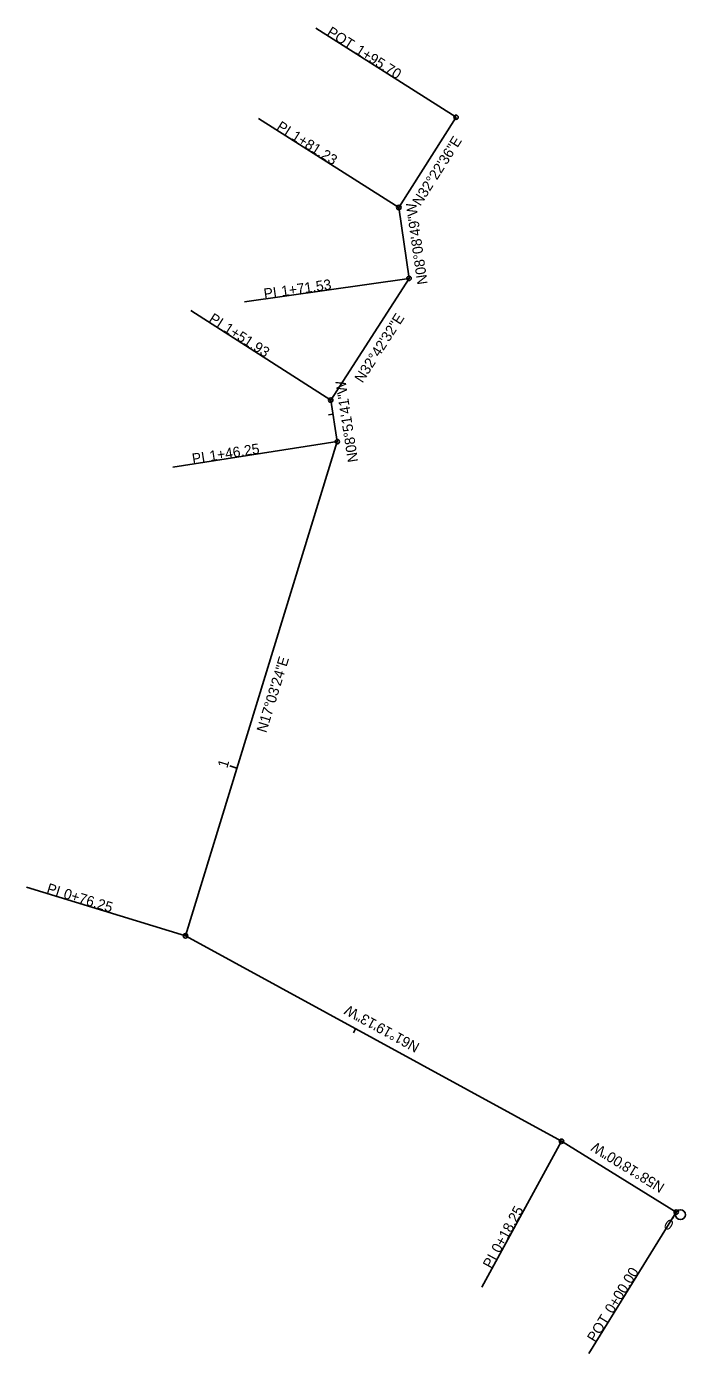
# Model space of a CAD drawing. Extents: x 2352406 to 2352495, y 726592 to 726772.
import ezdxf

# ---------------------------------------------------------------- set-up
doc = ezdxf.new("R2010")
doc.units = 0
for name, color, linetype in [('GE_P_Alignment', 7, 'Continuous'), ('GE_P_Driveway_CL', 7, 'Continuous'), ('SC_Scratch10', 7, 'Continuous'), ('SC_Scratch2', 7, 'Continuous'), ('SC_Scratch3', 7, 'Continuous'), ('SC_Scratch5', 7, 'Continuous'), ('VG_P_Cells', 7, 'Continuous')]:
    doc.layers.add(name, color=color, linetype=linetype)

msp = doc.modelspace()

# ---------------------------------------------------------------- linework, layer by layer
at = {"layer": 'GE_P_Alignment'}
for p, q in [((2352456.22, 726747.62), (2352463.97, 726759.83)), ((2352457.6, 726738.01), (2352456.22, 726747.62)), ((2352447.01, 726721.52), (2352457.6, 726738.01)), ((2352447.89, 726715.9), (2352447.01, 726721.52)), ((2352427.35, 726648.98), (2352447.89, 726715.9)), ((2352478.24, 726621.15), (2352427.35, 726648.98)), ((2352493.76, 726611.56), (2352478.24, 726621.15))]:
    msp.add_line(p, q, dxfattribs=at)
msp.add_circle((2352494.33, 726611.21), 0.672, dxfattribs=at)
at = {"layer": 'SC_Scratch2'}
for p, q in [((2352463.97, 726759.83), (2352444.97, 726771.88)), ((2352456.22, 726747.62), (2352437.22, 726759.67)), ((2352457.6, 726738.01), (2352435.33, 726734.82)), ((2352447.01, 726721.52), (2352428.08, 726733.68)), ((2352447.31, 726719.61), (2352446.71, 726719.52)), ((2352447.89, 726715.9), (2352425.65, 726712.44)), ((2352434.32, 726671.69), (2352433.36, 726671.98)), ((2352427.35, 726648.98), (2352405.84, 726655.58)), ((2352450.38, 726636.39), (2352450.09, 726635.86)), ((2352478.24, 726621.15), (2352467.44, 726601.41)), ((2352493.76, 726611.56), (2352481.94, 726592.42)), ((2352493.76, 726611.56), (2352493.24, 726610.71))]:
    msp.add_line(p, q, dxfattribs=at)
for centre in [(2352463.97, 726759.83), (2352456.22, 726747.62), (2352457.6, 726738.01), (2352447.01, 726721.52), (2352447.89, 726715.9), (2352427.35, 726648.98), (2352478.24, 726621.15), (2352493.76, 726611.56)]:
    msp.add_circle(centre, 0.3, dxfattribs=at)
at = {"layer": 'SC_Scratch5'}
for p, q in [((2352463.97, 726759.83), (2352444.97, 726771.88)), ((2352456.22, 726747.62), (2352437.22, 726759.67)), ((2352457.6, 726738.01), (2352435.33, 726734.82)), ((2352447.01, 726721.52), (2352428.08, 726733.68)), ((2352447.89, 726715.9), (2352425.65, 726712.44)), ((2352427.35, 726648.98), (2352405.84, 726655.58)), ((2352478.24, 726621.15), (2352467.44, 726601.41)), ((2352493.76, 726611.56), (2352481.94, 726592.42)), ((2352493.76, 726611.56), (2352493.24, 726610.71))]:
    msp.add_line(p, q, dxfattribs=at)
for centre in [(2352463.97, 726759.83), (2352456.22, 726747.62), (2352457.6, 726738.01), (2352447.01, 726721.52), (2352447.89, 726715.9), (2352427.35, 726648.98), (2352478.24, 726621.15), (2352493.76, 726611.56)]:
    msp.add_circle(centre, 0.3, dxfattribs=at)
at = {"layer": 'VG_P_Cells'}
for p, q in [((2352463.97, 726759.83), (2352444.97, 726771.88)), ((2352456.22, 726747.62), (2352437.22, 726759.67)), ((2352457.6, 726738.01), (2352435.33, 726734.82)), ((2352447.01, 726721.52), (2352428.08, 726733.68)), ((2352447.89, 726715.9), (2352425.65, 726712.44)), ((2352434.32, 726671.69), (2352433.75, 726671.87)), ((2352427.35, 726648.98), (2352405.84, 726655.58)), ((2352478.24, 726621.15), (2352467.44, 726601.41)), ((2352493.76, 726611.56), (2352481.94, 726592.42)), ((2352493.76, 726611.56), (2352493.24, 726610.71))]:
    msp.add_line(p, q, dxfattribs=at)
for centre in [(2352463.97, 726759.83), (2352456.22, 726747.62), (2352457.6, 726738.01), (2352447.01, 726721.52), (2352447.89, 726715.9), (2352427.35, 726648.98), (2352478.24, 726621.15), (2352493.76, 726611.56)]:
    msp.add_circle(centre, 0.3, dxfattribs=at)

# ---------------------------------------------------------------- texts
at = {"layer": 'GE_P_Driveway_CL'}
for s, rotation, p in [('N32°22\'36"E', 57.6234, (2352459.13, 726747.72)), ('N08°08\'49"W', 98.147, (2352460.13, 726737.28)), ('N32°42\'32"E', 57.2911, (2352451.3, 726723.76)), ('N08°51\'41"W', 98.8613, (2352450.73, 726713.22)), ('N17°03\'24"E', 72.9432, (2352438.27, 726676.39)), ('N61°19\'13"W', 151.3204, (2352459.15, 726634.32)), ('N58°18\'00"W', 148.2999, (2352492.31, 726615.28))]:
    msp.add_text(s, height=1.4, rotation=rotation, dxfattribs=at).set_placement(p)
at = {"layer": 'SC_Scratch10'}
for s, rotation, p in [('N32°22\'36"E', 57.6234, (2352459.13, 726747.72)), ('N08°08\'49"W', 98.147, (2352460.13, 726737.28)), ('N32°42\'32"E', 57.2911, (2352451.3, 726723.76)), ('N08°51\'41"W', 98.8613, (2352450.73, 726713.22)), ('N17°03\'24"E', 72.9432, (2352438.27, 726676.39)), ('N61°19\'13"W', 151.3204, (2352459.15, 726634.32)), ('N58°18\'00"W', 148.2999, (2352492.31, 726615.28))]:
    msp.add_text(s, height=1.4, rotation=rotation, dxfattribs=at).set_placement(p)
at = {"layer": 'SC_Scratch2'}
for s, rotation, p in [('POT', 327.6234, (2352446.37, 726771.02)), ('1+95.70', 327.6234, (2352450.23, 726768.57)), ('PI', 327.6234, (2352439.55, 726758.22)), ('1+81.23', 327.6234, (2352441.57, 726756.94)), ('1+71.53', 8.147, (2352440.41, 726735.57)), ('PI', 8.147, (2352438.04, 726735.23)), ('PI', 327.2911, (2352430.4, 726732.22)), ('1+51.93', 327.2911, (2352432.41, 726730.92)), ('1+46.25', 8.8613, (2352430.71, 726713.25)), ('PI', 8.8613, (2352428.35, 726712.88)), ('1', 72.9432, (2352432.99, 726671.61)), ('PI', 342.9432, (2352408.46, 726654.8)), ('0+76.25', 342.9432, (2352410.74, 726654.1)), ('0+18.25', 61.3204, (2352469.88, 726605.91)), ('0', 148.2999, (2352493.56, 726610.18)), ('PI', 61.3204, (2352468.73, 726603.81)), ('0+00.00', 58.2999, (2352485.18, 726597.71)), ('POT', 58.2999, (2352482.79, 726593.83))]:
    msp.add_text(s, height=1.4, rotation=rotation, dxfattribs=at).set_placement(p)
at = {"layer": 'SC_Scratch3'}
for s, rotation, p in [('N32°22\'36"E', 57.6234, (2352459.13, 726747.72)), ('N08°08\'49"W', 98.147, (2352460.13, 726737.28)), ('N32°42\'32"E', 57.2911, (2352451.3, 726723.76)), ('N08°51\'41"W', 98.8613, (2352450.73, 726713.22)), ('N17°03\'24"E', 72.9432, (2352438.27, 726676.39)), ('N61°19\'13"W', 151.3204, (2352459.15, 726634.32)), ('N58°18\'00"W', 148.2999, (2352492.31, 726615.28))]:
    msp.add_text(s, height=1.4, rotation=rotation, dxfattribs=at).set_placement(p)
at = {"layer": 'SC_Scratch5'}
for s, rotation, p in [('POT', 327.6234, (2352446.37, 726771.02)), ('1+95.70', 327.6234, (2352450.23, 726768.57)), ('PI', 327.6234, (2352439.55, 726758.22)), ('1+81.23', 327.6234, (2352441.57, 726756.94)), ('1+71.53', 8.147, (2352440.41, 726735.57)), ('PI', 8.147, (2352438.04, 726735.23)), ('PI', 327.2911, (2352430.4, 726732.22)), ('1+51.93', 327.2911, (2352432.41, 726730.92)), ('1+46.25', 8.8613, (2352430.71, 726713.25)), ('PI', 8.8613, (2352428.35, 726712.88)), ('PI', 342.9432, (2352408.46, 726654.8)), ('0+76.25', 342.9432, (2352410.74, 726654.1)), ('0+18.25', 61.3204, (2352469.88, 726605.91)), ('0', 148.2999, (2352493.56, 726610.18)), ('PI', 61.3204, (2352468.73, 726603.81)), ('0+00.00', 58.2999, (2352485.18, 726597.71)), ('POT', 58.2999, (2352482.79, 726593.83))]:
    msp.add_text(s, height=1.4, rotation=rotation, dxfattribs=at).set_placement(p)
at = {"layer": 'VG_P_Cells'}
for s, rotation, p in [('POT', 327.6234, (2352446.37, 726771.02)), ('1+95.70', 327.6234, (2352450.23, 726768.57)), ('PI', 327.6234, (2352439.55, 726758.22)), ('1+81.23', 327.6234, (2352441.57, 726756.94)), ('1+71.53', 8.147, (2352440.41, 726735.57)), ('PI', 8.147, (2352438.04, 726735.23)), ('PI', 327.2911, (2352430.4, 726732.22)), ('1+51.93', 327.2911, (2352432.41, 726730.92)), ('1+46.25', 8.8613, (2352430.71, 726713.25)), ('PI', 8.8613, (2352428.35, 726712.88)), ('PI', 342.9432, (2352408.46, 726654.8)), ('0+76.25', 342.9432, (2352410.74, 726654.1)), ('0+18.25', 61.3204, (2352469.88, 726605.91)), ('0', 148.2999, (2352493.56, 726610.18)), ('PI', 61.3204, (2352468.73, 726603.81)), ('0+00.00', 58.2999, (2352485.18, 726597.71)), ('POT', 58.2999, (2352482.79, 726593.83))]:
    msp.add_text(s, height=1.4, rotation=rotation, dxfattribs=at).set_placement(p)

doc.saveas('drawing.dxf')
